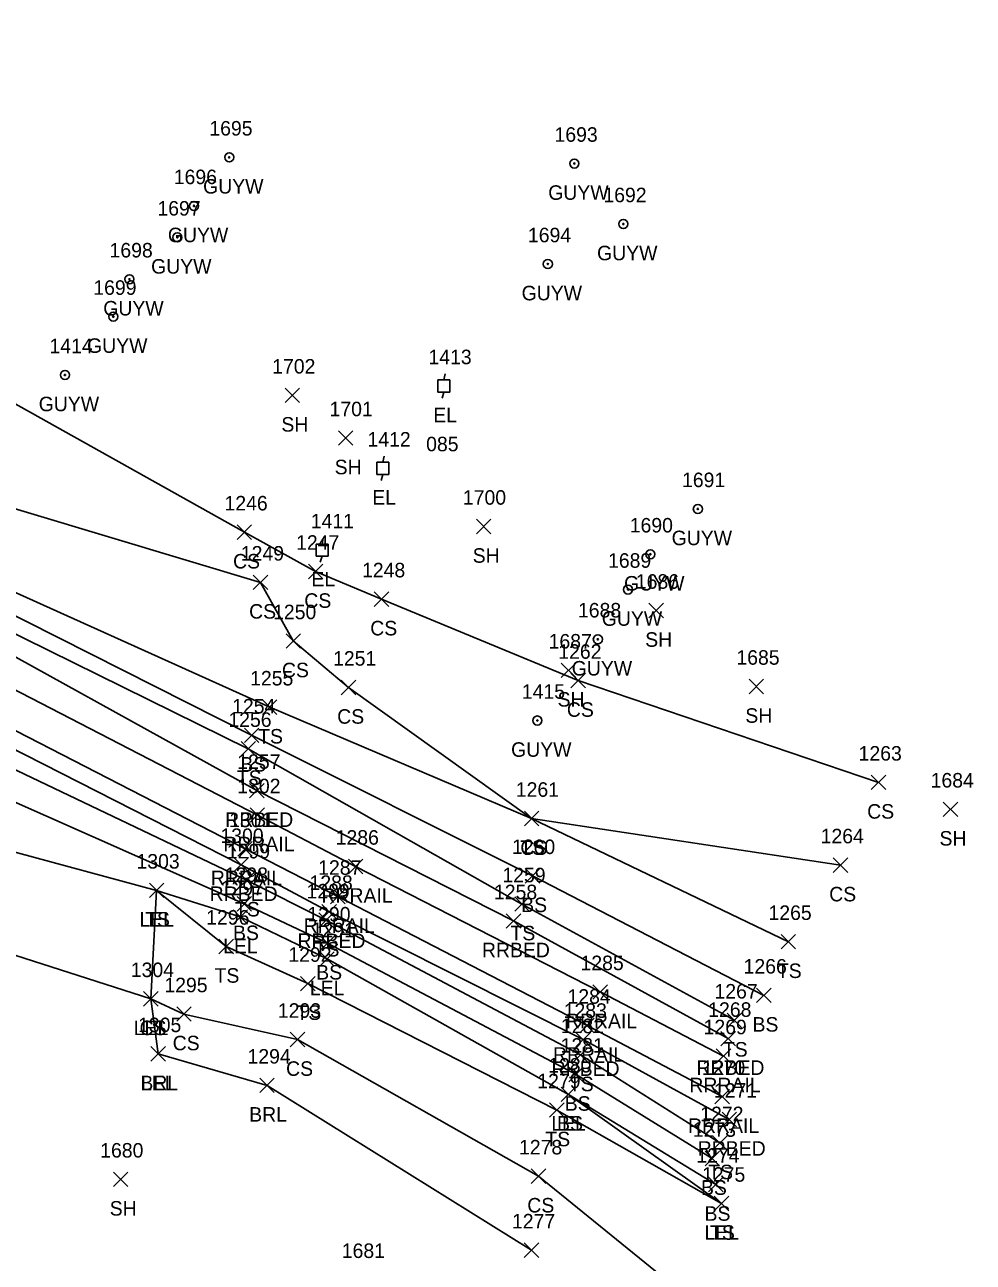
# Model space of a CAD drawing. Extents: x 1443960 to 1446865, y 610387 to 616706.
# Drawn here: x 1446734.6 to 1446865.2, y 611000.1 to 611170.6 of the extents above; entities that cross this region are included whole.
import ezdxf

# ---------------------------------------------------------------- set-up
doc = ezdxf.new("R2010")
doc.units = 0
for name, color, linetype in [('L_A', 7, 'Continuous'), ('L_I', 7, 'Continuous'), ('L_TIC', 7, 'Continuous'), ('LABL', 7, 'Continuous'), ('LARO', 7, 'Continuous'), ('LELB', 7, 'Continuous'), ('R_A', 7, 'Continuous'), ('R_I', 7, 'Continuous'), ('R_TIC', 7, 'Continuous'), ('RR', 7, 'Continuous'), ('RRB', 7, 'Continuous'), ('U_A', 7, 'Continuous'), ('U_C', 7, 'Continuous'), ('U_I', 7, 'Continuous'), ('UEPT', 7, 'Continuous'), ('UPGW', 7, 'Continuous')]:
    doc.layers.add(name, color=color, linetype=linetype)

msp = doc.modelspace()

# ---------------------------------------------------------------- linework, layer by layer
at = {"layer": 'L_TIC'}
for points in [[(1446770.41, 611118.55), (1446772.41, 611120.55)], [(1446772.41, 611118.55), (1446770.41, 611120.55)], [(1446777.75, 611112.67), (1446779.75, 611114.67)], [(1446779.75, 611112.67), (1446777.75, 611114.67)], [(1446763.81, 611099.69), (1446765.81, 611101.69)], [(1446765.81, 611099.69), (1446763.81, 611101.69)], [(1446796.76, 611100.48), (1446798.76, 611102.48)], [(1446798.76, 611100.48), (1446796.76, 611102.48)], [(1446773.62, 611094.27), (1446775.62, 611096.27)], [(1446775.62, 611094.27), (1446773.62, 611096.27)], [(1446766.02, 611092.78), (1446768.02, 611094.78)], [(1446768.02, 611092.78), (1446766.02, 611094.78)], [(1446782.7, 611090.47), (1446784.7, 611092.47)], [(1446784.7, 611090.47), (1446782.7, 611092.47)], [(1446820.52, 611088.9), (1446822.52, 611090.9)], [(1446822.52, 611088.9), (1446820.52, 611090.9)], [(1446770.54, 611084.7), (1446772.54, 611086.7)], [(1446772.54, 611084.7), (1446770.54, 611086.7)], [(1446808.45, 611080.66), (1446810.45, 611082.66)], [(1446810.45, 611080.66), (1446808.45, 611082.66)], [(1446809.78, 611079.25), (1446811.78, 611081.25)], [(1446811.78, 611079.25), (1446809.78, 611081.25)], [(1446778.15, 611078.3), (1446780.15, 611080.3)], [(1446780.15, 611078.3), (1446778.15, 611080.3)], [(1446834.31, 611078.43), (1446836.31, 611080.43)], [(1446836.31, 611078.43), (1446834.31, 611080.43)], [(1446767.29, 611075.57), (1446769.29, 611077.57)], [(1446769.29, 611075.57), (1446767.29, 611077.57)], [(1446764.81, 611071.71), (1446766.81, 611073.71)], [(1446766.81, 611071.71), (1446764.81, 611073.71)], [(1446764.35, 611069.86), (1446766.35, 611071.86)], [(1446766.35, 611069.86), (1446764.35, 611071.86)], [(1446851.14, 611065.22), (1446853.14, 611067.22)], [(1446853.14, 611065.22), (1446851.14, 611067.22)], [(1446861.06, 611061.51), (1446863.06, 611063.51)], [(1446863.06, 611061.51), (1446861.06, 611063.51)], [(1446803.37, 611060.23), (1446805.37, 611062.23)], [(1446805.37, 611060.23), (1446803.37, 611062.23)], [(1446803.37, 611060.23), (1446805.37, 611062.23)], [(1446805.37, 611060.23), (1446803.37, 611062.23)], [(1446845.91, 611053.82), (1446847.91, 611055.82)], [(1446847.91, 611053.82), (1446845.91, 611055.82)], [(1446764.1, 611051.74), (1446766.1, 611053.74)], [(1446766.1, 611051.74), (1446764.1, 611053.74)], [(1446803.49, 611052.34), (1446805.49, 611054.34)], [(1446805.49, 611052.34), (1446803.49, 611054.34)], [(1446751.72, 611050.34), (1446753.72, 611052.34)], [(1446753.72, 611050.34), (1446751.72, 611052.34)], [(1446751.72, 611050.34), (1446753.72, 611052.34)], [(1446753.72, 611050.34), (1446751.72, 611052.34)], [(1446763.8, 611048.49), (1446765.8, 611050.49)], [(1446765.8, 611048.49), (1446763.8, 611050.49)], [(1446802.04, 611048.45), (1446804.04, 611050.45)], [(1446804.04, 611048.45), (1446802.04, 611050.45)], [(1446763.24, 611046.67), (1446765.24, 611048.67)], [(1446765.24, 611046.67), (1446763.24, 611048.67)], [(1446775.07, 611046.22), (1446777.07, 611048.22)], [(1446777.07, 611046.22), (1446775.07, 611048.22)], [(1446775.26, 611043.05), (1446777.26, 611045.05)], [(1446777.26, 611043.05), (1446775.26, 611045.05)], [(1446838.73, 611043.26), (1446840.73, 611045.26)], [(1446840.73, 611043.26), (1446838.73, 611045.26)], [(1446761.29, 611042.61), (1446763.29, 611044.61)], [(1446763.29, 611042.61), (1446761.29, 611044.61)], [(1446775.19, 611040.88), (1446777.19, 611042.88)], [(1446777.19, 611040.88), (1446775.19, 611042.88)], [(1446772.55, 611037.49), (1446774.55, 611039.49)], [(1446774.55, 611037.49), (1446772.55, 611039.49)], [(1446835.35, 611035.87), (1446837.35, 611037.87)], [(1446837.35, 611035.87), (1446835.35, 611037.87)], [(1446750.93, 611035.39), (1446752.93, 611037.39)], [(1446752.93, 611035.39), (1446750.93, 611037.39)], [(1446750.93, 611035.39), (1446752.93, 611037.39)], [(1446752.93, 611035.39), (1446750.93, 611037.39)], [(1446755.49, 611033.3), (1446757.49, 611035.3)], [(1446757.49, 611033.3), (1446755.49, 611035.3)], [(1446831.29, 611032.43), (1446833.29, 611034.43)], [(1446833.29, 611032.43), (1446831.29, 611034.43)], [(1446771.11, 611029.78), (1446773.11, 611031.78)], [(1446773.11, 611029.78), (1446771.11, 611031.78)], [(1446751.94, 611027.8), (1446753.94, 611029.8)], [(1446753.94, 611027.8), (1446751.94, 611029.8)], [(1446751.94, 611027.8), (1446753.94, 611029.8)], [(1446753.94, 611027.8), (1446751.94, 611029.8)], [(1446810.1, 611027.66), (1446812.1, 611029.66)], [(1446812.1, 611027.66), (1446810.1, 611029.66)], [(1446809.48, 611024.97), (1446811.48, 611026.97)], [(1446811.48, 611024.97), (1446809.48, 611026.97)], [(1446766.93, 611023.47), (1446768.93, 611025.47)], [(1446768.93, 611023.47), (1446766.93, 611025.47)], [(1446808.43, 611022.23), (1446810.43, 611024.23)], [(1446810.43, 611022.23), (1446808.43, 611024.23)], [(1446808.43, 611022.23), (1446810.43, 611024.23)], [(1446810.43, 611022.23), (1446808.43, 611024.23)], [(1446806.85, 611020.07), (1446808.85, 611022.07)], [(1446808.85, 611020.07), (1446806.85, 611022.07)], [(1446829.28, 611015.53), (1446831.28, 611017.53)], [(1446831.28, 611015.53), (1446829.28, 611017.53)], [(1446828.25, 611013.38), (1446830.25, 611015.38)], [(1446830.25, 611013.38), (1446828.25, 611015.38)], [(1446746.77, 611010.52), (1446748.77, 611012.52)], [(1446748.77, 611010.52), (1446746.77, 611012.52)], [(1446804.32, 611010.95), (1446806.32, 611012.95)], [(1446806.32, 611010.95), (1446804.32, 611012.95)], [(1446828.74, 611009.81), (1446830.74, 611011.81)], [(1446830.74, 611009.81), (1446828.74, 611011.81)], [(1446829.53, 611007.19), (1446831.53, 611009.19)], [(1446831.53, 611007.19), (1446829.53, 611009.19)], [(1446829.53, 611007.19), (1446831.53, 611009.19)], [(1446831.53, 611007.19), (1446829.53, 611009.19)], [(1446803.36, 611000.75), (1446805.36, 611002.75)], [(1446805.36, 611000.75), (1446803.36, 611002.75)]]:
    msp.add_lwpolyline(points, dxfattribs=at)
at = {"layer": 'LABL'}
msp.add_lwpolyline([(1446804.36, 611001.75), (1446767.93, 611024.47), (1446752.94, 611028.8)], dxfattribs=at)
at = {"layer": 'LARO'}
msp.add_lwpolyline([(1446830.53, 611008.19), (1446809.43, 611023.23), (1446776.19, 611041.88), (1446764.24, 611047.67), (1446752.72, 611051.34), (1446751.93, 611036.39), (1446752.94, 611028.8)], dxfattribs=at)
at = {"layer": 'LELB'}
for points in [[(1446650.95, 611452.22), (1446651.9, 611426.45), (1446649.87, 611385.11), (1446652.75, 611374.92), (1446649.16, 611347.4), (1446644.4, 611298.29), (1446641.62, 611252.48), (1446636.15, 611208.65), (1446631.11, 611163.63), (1446633.53, 611158.95), (1446637.37, 611162.3), (1446642.9, 611148.76), (1446645.64, 611144.28), (1446654.29, 611138.48), (1446692.29, 611116.85), (1446724.64, 611106.48), (1446767.02, 611093.78), (1446771.54, 611085.7), (1446779.15, 611079.3), (1446804.37, 611061.23), (1446846.91, 611054.82)], [(1446646.01, 611451.43), (1446645.8, 611427.91), (1446642.94, 611384.68), (1446641.12, 611344.07), (1446637.9, 611299.18), (1446633.76, 611254.36), (1446628.53, 611208.76), (1446626.59, 611161.02), (1446631.89, 611151.52), (1446639.4, 611144.52), (1446638.89, 611137.35), (1446641.22, 611135.35), (1446691.88, 611109.53), (1446720.61, 611092.87), (1446765.35, 611070.86), (1446803.04, 611049.45), (1446832.29, 611033.43)], [(1446674.41, 611451.43), (1446673.33, 611423.78), (1446673.4, 611405.75), (1446673.54, 611387.21), (1446676.96, 611378.49), (1446687.51, 611358.67), (1446682.52, 611348.73), (1446672.1, 611338.67), (1446667.43, 611325.36), (1446664.64, 611295.09), (1446664.71, 611246.97), (1446665.06, 611207.83), (1446662.27, 611160.47), (1446692.58, 611128.32), (1446729.03, 611120.7), (1446764.81, 611100.69), (1446774.62, 611095.27), (1446783.7, 611091.47), (1446810.78, 611080.25), (1446852.14, 611066.22)], [(1446830.28, 611016.53), (1446811.1, 611028.66), (1446776.07, 611047.22), (1446765.1, 611052.74), (1446718.13, 611075.14), (1446677.7, 611094.8), (1446645.56, 611110.93), (1446633.09, 611119.85), (1446623.05, 611121.28), (1446619.75, 611099.3), (1446617.85, 611081.96), (1446615.6, 611043.86), (1446614.77, 611002.83), (1446608.04, 610951.6), (1446605.01, 610902.95), (1446601.47, 610861.36)], [(1446829.25, 611014.38), (1446810.48, 611025.97), (1446776.26, 611044.05), (1446764.8, 611049.49), (1446716.62, 611070.84), (1446676.65, 611091.11), (1446643.97, 611105.98), (1446632.65, 611089.9), (1446628.97, 611091.61), (1446629.07, 611084.29), (1446632.07, 611081.47), (1446632.15, 611079.98), (1446631.66, 611078.24), (1446628.85, 611073.01), (1446626.96, 611043.36), (1446621.65, 611002.83), (1446619.79, 610952.72), (1446614.79, 610900.25), (1446612.14, 610862.12)], [(1446724.05, 611096.52), (1446768.29, 611076.57), (1446804.37, 611061.23), (1446839.73, 611044.26)], [(1446724.05, 611096.52), (1446725.85, 611092.88), (1446765.81, 611072.71), (1446804.49, 611053.34), (1446836.35, 611036.87)], [(1446830.53, 611008.19), (1446807.85, 611021.07), (1446773.55, 611038.49), (1446762.29, 611043.61), (1446752.72, 611051.34), (1446711.65, 611062.43), (1446674.23, 611080.27), (1446638.75, 611091.24), (1446639.39, 611078.57), (1446637.85, 611065.45), (1446634.87, 611042.47), (1446630.92, 611001.38), (1446634.24, 610953.7), (1446628.67, 610898.68), (1446624.68, 610861.11)], [(1446826.78, 610994.51), (1446805.32, 611011.95), (1446772.11, 611030.78), (1446756.49, 611034.3), (1446751.93, 611036.39), (1446704.53, 611051.58), (1446668.04, 611061.39), (1446654.45, 611063.68), (1446651.98, 611036.37), (1446649.42, 610997.32), (1446649.97, 610954.25), (1446649.35, 610895.51), (1446645.03, 610860.5)], [(1446829.74, 611010.81), (1446809.43, 611023.23)]]:
    msp.add_lwpolyline(points, dxfattribs=at)
at = {"layer": 'R_TIC'}
for points in [[(1446765.52, 611064.08), (1446767.52, 611066.08)], [(1446767.52, 611064.08), (1446765.52, 611066.08)], [(1446765.6, 611060.72), (1446767.6, 611062.72)], [(1446767.6, 611060.72), (1446765.6, 611062.72)], [(1446763.9, 611056.05), (1446765.9, 611058.05)], [(1446765.9, 611056.05), (1446763.9, 611058.05)], [(1446763.37, 611053.87), (1446765.37, 611055.87)], [(1446765.37, 611053.87), (1446763.37, 611055.87)], [(1446779.13, 611053.63), (1446781.13, 611055.63)], [(1446781.13, 611053.63), (1446779.13, 611055.63)], [(1446776.67, 611049.48), (1446778.67, 611051.48)], [(1446778.67, 611049.48), (1446776.67, 611051.48)], [(1446775.48, 611047.4), (1446777.48, 611049.4)], [(1446777.48, 611047.4), (1446775.48, 611049.4)], [(1446800.87, 611046.12), (1446802.87, 611048.12)], [(1446802.87, 611046.12), (1446800.87, 611048.12)], [(1446812.8, 611036.34), (1446814.8, 611038.34)], [(1446814.8, 611036.34), (1446812.8, 611038.34)], [(1446811, 611031.72), (1446813, 611033.72)], [(1446813, 611031.72), (1446811, 611033.72)], [(1446810.47, 611029.77), (1446812.47, 611031.77)], [(1446812.47, 611029.77), (1446810.47, 611031.77)], [(1446830.43, 611029.91), (1446832.43, 611031.91)], [(1446832.43, 611029.91), (1446830.43, 611031.91)], [(1446829.8, 611027.51), (1446831.8, 611029.51)], [(1446831.8, 611027.51), (1446829.8, 611029.51)], [(1446829.61, 611021.91), (1446831.61, 611023.91)], [(1446831.61, 611021.91), (1446829.61, 611023.91)], [(1446830.59, 611018.77), (1446832.59, 611020.77)], [(1446832.59, 611018.77), (1446830.59, 611020.77)]]:
    msp.add_lwpolyline(points, dxfattribs=at)
at = {"layer": 'RR'}
for points in [[(1446830.8, 611028.51), (1446813.8, 611037.34), (1446780.13, 611054.63), (1446766.6, 611061.72), (1446723.16, 611084.18), (1446681.83, 611105.5), (1446667.65, 611112.72), (1446650.45, 611121.75), (1446635.82, 611129.05), (1446620.36, 611137.27), (1446611.04, 611142.08), (1446598.97, 611148.35), (1446587.47, 611154.32), (1446577.27, 611159.61), (1446545.1, 611176.06), (1446537.95, 611179.67), (1446530.32, 611183.72), (1446472.23, 611213.59), (1446430.68, 611235.02), (1446393.22, 611254.19), (1446353.39, 611274.79), (1446345.67, 611278.8)], [(1446830.61, 611022.91), (1446812, 611032.72), (1446777.67, 611050.48), (1446764.9, 611057.05), (1446720.8, 611079.76), (1446679.61, 611101.04), (1446672.6, 611104.75), (1446648.09, 611117.4), (1446634.05, 611124.73), (1446619.04, 611132.42), (1446610.71, 611136.75), (1446598.39, 611142.94), (1446586.96, 611148.93), (1446576.92, 611154.08), (1446541.41, 611172.48), (1446511.36, 611187.89), (1446469.88, 611209.21), (1446428.54, 611230.42), (1446391.04, 611249.76), (1446351.07, 611270.34), (1446343.04, 611274.54)]]:
    msp.add_lwpolyline(points, dxfattribs=at)
at = {"layer": 'RRB'}
for points in [[(1446632.76, 611134.38), (1446690.22, 611104.37), (1446720.36, 611090.64), (1446766.52, 611065.08), (1446801.87, 611047.12), (1446831.43, 611030.91)], [(1446831.59, 611019.77), (1446811.47, 611030.77), (1446776.48, 611048.4), (1446764.37, 611054.87), (1446719.7, 611077.58), (1446678.83, 611099.24), (1446647.24, 611114.98), (1446628.17, 611124.39)]]:
    msp.add_lwpolyline(points, dxfattribs=at)
at = {"layer": 'UEPT'}
for p, q in [((1446791.45, 611120), (1446791.45, 611121.67)), ((1446791.45, 611121.67), (1446793.11, 611121.67)), ((1446792.45, 611122.5), (1446792.28, 611121.67)), ((1446793.11, 611121.67), (1446793.11, 611120)), ((1446793.11, 611120), (1446791.45, 611120)), ((1446792.03, 611119.17), (1446792.28, 611120)), ((1446792.28, 611120.84), (1446792.28, 611120.84)), ((1446784.05, 611111.15), (1446783.88, 611110.32)), ((1446783.05, 611108.65), (1446783.05, 611110.32)), ((1446783.05, 611110.32), (1446784.72, 611110.32)), ((1446783.88, 611109.49), (1446783.88, 611109.49)), ((1446784.72, 611110.32), (1446784.72, 611108.65)), ((1446784.72, 611108.65), (1446783.05, 611108.65)), ((1446783.63, 611107.82), (1446783.88, 611108.65)), ((1446775.68, 611099.89), (1446775.51, 611099.05)), ((1446774.68, 611097.39), (1446774.68, 611099.05)), ((1446774.68, 611099.05), (1446776.34, 611099.05)), ((1446775.51, 611098.22), (1446775.51, 611098.22)), ((1446776.34, 611099.05), (1446776.34, 611097.39)), ((1446776.34, 611097.39), (1446774.68, 611097.39)), ((1446775.26, 611096.55), (1446775.51, 611097.39))]:
    msp.add_line(p, q, dxfattribs=at)
at = {"layer": 'UPGW'}
for centre, radius in [((1446762.72, 611152.35), 0.625), ((1446762.72, 611152.35), 0.0833), ((1446810.26, 611151.49), 0.625), ((1446810.26, 611151.49), 0.0833), ((1446757.88, 611145.65), 0.625), ((1446757.88, 611145.65), 0.0833), ((1446816.99, 611143.16), 0.625), ((1446755.57, 611141.32), 0.625), ((1446816.99, 611143.16), 0.0833), ((1446755.57, 611141.32), 0.0833), ((1446806.6, 611137.64), 0.625), ((1446806.6, 611137.64), 0.0833), ((1446748.98, 611135.55), 0.625), ((1446748.98, 611135.55), 0.0833), ((1446746.75, 611130.4), 0.625), ((1446746.75, 611130.4), 0.0833), ((1446740.09, 611122.36), 0.625), ((1446740.09, 611122.36), 0.0833), ((1446827.26, 611103.9), 0.625), ((1446827.26, 611103.9), 0.0833), ((1446820.71, 611097.65), 0.625), ((1446820.71, 611097.65), 0.0833), ((1446817.64, 611092.79), 0.625), ((1446817.64, 611092.79), 0.0833), ((1446813.49, 611085.94), 0.625), ((1446813.49, 611085.94), 0.0833), ((1446805.15, 611074.74), 0.625), ((1446805.15, 611074.74), 0.0833)]:
    msp.add_circle(centre, radius, dxfattribs=at)

# ---------------------------------------------------------------- texts
at = {"layer": 'L_A'}
for s, p in [('SH', (1446769.9, 611114.55)), ('SH', (1446777.24, 611108.67)), ('CS', (1446763.25, 611095.69)), ('SH', (1446796.25, 611096.48)), ('CS', (1446765.46, 611088.78)), ('CS', (1446773.06, 611090.27)), ('CS', (1446782.14, 611086.47)), ('SH', (1446820.01, 611084.9)), ('CS', (1446769.98, 611080.7)), ('SH', (1446807.94, 611076.66)), ('CS', (1446809.22, 611075.25)), ('CS', (1446777.59, 611074.3)), ('SH', (1446833.8, 611074.43)), ('TS', (1446766.7, 611071.57)), ('BS', (1446764.25, 611067.71)), ('TS', (1446763.76, 611065.86)), ('CS', (1446850.58, 611061.22)), ('SH', (1446860.54, 611057.51)), ('TS', (1446802.78, 611056.23)), ('CS', (1446802.81, 611056.23)), ('CS', (1446845.35, 611049.82)), ('TS', (1446763.51, 611047.74)), ('BS', (1446802.93, 611048.34)), ('LEL', (1446750.36, 611046.34)), ('TS', (1446751.13, 611046.34)), ('BS', (1446763.24, 611044.49)), ('TS', (1446801.45, 611044.45)), ('LEL', (1446761.88, 611042.67)), ('TS', (1446774.48, 611042.22)), ('TS', (1446838.14, 611039.26)), ('TS', (1446760.7, 611038.61)), ('BS', (1446774.7, 611039.05)), ('LEL', (1446773.83, 611036.88)), ('TS', (1446771.96, 611033.49)), ('LEL', (1446749.57, 611031.39)), ('CS', (1446750.37, 611031.39)), ('BS', (1446834.79, 611031.87)), ('CS', (1446754.93, 611029.3)), ('TS', (1446830.7, 611028.43)), ('CS', (1446770.55, 611025.78)), ('BRL', (1446750.48, 611023.8)), ('LEL', (1446750.58, 611023.8)), ('TS', (1446809.5, 611023.66)), ('BS', (1446808.93, 611020.97)), ('BRL', (1446765.47, 611019.47)), ('LEL', (1446807.07, 611018.23)), ('BS', (1446807.87, 611018.23)), ('TS', (1446806.26, 611016.07)), ('TS', (1446828.69, 611011.53)), ('BS', (1446827.69, 611009.38)), ('CS', (1446803.77, 611006.95)), ('SH', (1446746.26, 611006.52)), ('BS', (1446828.18, 611005.81)), ('LEL', (1446828.17, 611003.19)), ('TS', (1446828.94, 611003.19))]:
    msp.add_text(s, height=2, dxfattribs=at).set_placement(p)
at = {"layer": 'L_I'}
for s, p in [('1702', (1446768.64, 611122.55)), ('1701', (1446776.54, 611116.67)), ('1700', (1446794.9, 611104.48)), ('1246', (1446762.07, 611103.69)), ('1247', (1446771.93, 611098.27)), ('1249', (1446764.32, 611096.78)), ('1248', (1446781.01, 611094.47)), ('1686', (1446818.72, 611092.9)), ('1250', (1446768.76, 611088.7)), ('1687', (1446806.71, 611084.66)), ('1251', (1446777.02, 611082.3)), ('1262', (1446808.04, 611083.25)), ('1685', (1446832.57, 611082.43)), ('1255', (1446765.6, 611079.57)), ('1254', (1446763.12, 611075.71)), ('1256', (1446762.6, 611073.86)), ('1263', (1446849.4, 611069.22)), ('1684', (1446859.32, 611065.51)), ('1261', (1446802.19, 611064.23)), ('1261', (1446802.19, 611064.23)), ('1260', (1446801.66, 611056.34)), ('1264', (1446844.17, 611057.82)), ('1299', (1446762.4, 611055.74)), ('1303', (1446749.95, 611054.34)), ('1303', (1446749.95, 611054.34)), ('1298', (1446762.11, 611052.49)), ('1259', (1446800.34, 611052.45)), ('1297', (1446761.55, 611050.67)), ('1289', (1446773.37, 611050.22)), ('1296', (1446759.55, 611046.61)), ('1290', (1446773.48, 611047.05)), ('1265', (1446836.99, 611047.26)), ('1291', (1446774.07, 611044.88)), ('1292', (1446770.86, 611041.49)), ('1304', (1446749.16, 611039.39)), ('1304', (1446749.16, 611039.39)), ('1266', (1446833.56, 611039.87)), ('1295', (1446753.79, 611037.3)), ('1267', (1446829.55, 611036.43)), ('1293', (1446769.42, 611033.78)), ('1305', (1446750.17, 611031.8)), ('1305', (1446750.17, 611031.8)), ('1282', (1446808.4, 611031.66)), ('1294', (1446765.24, 611027.47)), ('1281', (1446808.36, 611028.97)), ('1280', (1446806.65, 611026.23)), ('1280', (1446806.65, 611026.23)), ('1279', (1446805.15, 611024.07)), ('1272', (1446827.59, 611019.53)), ('1273', (1446826.56, 611017.38)), ('1680', (1446744.95, 611014.52)), ('1278', (1446802.63, 611014.95)), ('1274', (1446827.05, 611013.81)), ('1275', (1446827.84, 611011.19)), ('1275', (1446827.84, 611011.19)), ('1277', (1446801.66, 611004.75)), ('1681', (1446778.22, 611000.68))]:
    msp.add_text(s, height=2, dxfattribs=at).set_placement(p)
at = {"layer": 'R_A'}
for s, p in [('RRBED', (1446762.17, 611060.08)), ('RRRAIL', (1446761.9, 611056.72)), ('RRRAIL', (1446760.19, 611052.05)), ('RRBED', (1446760.02, 611049.87)), ('RRRAIL', (1446775.42, 611049.63)), ('RRRAIL', (1446772.96, 611045.48)), ('RRBED', (1446772.12, 611043.4)), ('RRBED', (1446797.52, 611042.12)), ('RRRAIL', (1446809.09, 611032.34)), ('RRRAIL', (1446807.3, 611027.72)), ('RRBED', (1446807.12, 611025.77)), ('RRBED', (1446827.07, 611025.91)), ('RRRAIL', (1446826.09, 611023.51)), ('RRRAIL', (1446825.9, 611017.91)), ('RRBED', (1446827.24, 611014.77))]:
    msp.add_text(s, height=2, dxfattribs=at).set_placement(p)
at = {"layer": 'R_I'}
for s, p in [('1257', (1446763.83, 611068.08)), ('1302', (1446763.83, 611064.72)), ('1301', (1446762.69, 611060.05)), ('1300', (1446761.51, 611057.87)), ('1286', (1446777.38, 611057.63)), ('1287', (1446774.97, 611053.48)), ('1288', (1446773.78, 611051.4)), ('1258', (1446799.18, 611050.12)), ('1285', (1446811.1, 611040.34)), ('1284', (1446809.31, 611035.72)), ('1283', (1446808.78, 611033.77)), ('1268', (1446828.69, 611033.91)), ('1269', (1446828.05, 611031.51)), ('1270', (1446827.83, 611025.91)), ('1271', (1446829.47, 611022.77))]:
    msp.add_text(s, height=2, dxfattribs=at).set_placement(p)
at = {"layer": 'U_A'}
for s, p in [('GUYW', (1446759.12, 611147.35)), ('GUYW', (1446806.65, 611146.49)), ('GUYW', (1446754.27, 611140.65)), ('GUYW', (1446813.38, 611138.16)), ('GUYW', (1446751.96, 611136.32)), ('GUYW', (1446802.99, 611132.64)), ('GUYW', (1446745.37, 611130.55)), ('GUYW', (1446743.14, 611125.4)), ('GUYW', (1446736.48, 611117.36)), ('EL', (1446790.82, 611115.84)), ('EL', (1446782.42, 611104.49)), ('GUYW', (1446823.65, 611098.9)), ('EL', (1446774.04, 611093.22)), ('GUYW', (1446817.1, 611092.65)), ('GUYW', (1446814.03, 611087.79)), ('GUYW', (1446809.89, 611080.94)), ('GUYW', (1446801.54, 611069.74))]:
    msp.add_text(s, height=2, dxfattribs=at).set_placement(p)
at = {"layer": 'U_C'}
msp.add_text('085', height=2, dxfattribs=at).set_placement((1446789.84, 611111.84))
at = {"layer": 'U_I'}
for s, p in [('1695', (1446759.98, 611155.35)), ('1693', (1446807.52, 611154.49)), ('1696', (1446755.08, 611148.65)), ('1692', (1446814.25, 611146.16)), ('1697', (1446752.83, 611144.32)), ('1694', (1446803.86, 611140.64)), ('1698', (1446746.24, 611138.55)), ('1699', (1446744, 611133.4)), ('1414', (1446737.96, 611125.36)), ('1413', (1446790.16, 611123.84)), ('1412', (1446781.76, 611112.49)), ('1691', (1446825.08, 611106.9)), ('1411', (1446773.95, 611101.22)), ('1690', (1446817.88, 611100.65)), ('1689', (1446814.89, 611095.79)), ('1688', (1446810.75, 611088.94)), ('1415', (1446803.02, 611077.74))]:
    msp.add_text(s, height=2, dxfattribs=at).set_placement(p)

doc.saveas('drawing.dxf')
